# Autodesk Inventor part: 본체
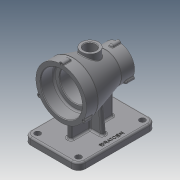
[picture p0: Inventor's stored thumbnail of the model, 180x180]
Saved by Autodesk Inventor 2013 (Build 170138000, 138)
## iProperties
Created: 2020-03
Part Number: 본체
Material: Generic
Document SubType Name: Modeling
Designer: user
Density: 1 g/cm^3
Author: user
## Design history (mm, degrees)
sketch "스케치5"
  geometry: L1 (-50, 44)-(-30, 44); L2 (-30, 44)-(27, 27.5); L3 (27, 27.5)-(50, 27.5); L4 (50, 27.5)-(50, 0); L5 (50, 0)-(-50, 0); L6 (-50, 0)-(-50, 44); 2 further points
  constraints: 12 end point, 3 parallel, 1 coincident, 1 horizontal, 1 midpoint, 1 perpendicular
  dimensions: "d25" = 20 distance of L1.start L1.end; "d27" = 77 distance from line of L2.end L6; "d28" = 100 distance between parallel lines of L4 L6; "d29" = 88 diameter of L1 L5; "d30" = 55 diameter of L3 L5
revolve "회전2" sketch "스케치5" stored, may be unused: angle "d31" = 90 deg
sketch "스케치6"
  geometry: C1 r 44 at (0, 0) reference; C2 r 36 at (0, 0)
  constraints: 1 centre point, 1 coincident
  dimensions: "d32" = 72 diameter of C2
extrude "돌출4" cut sketch "스케치6" distance "d34" = 23; taper "d35" = 0 deg
sketch "스케치7"
  geometry: C1 r 36 at (0, 0) reference; C2 r 26 at (0, 0)
  constraints: 1 centre point, 1 coincident
  dimensions: "d36" = 52 diameter of C2
extrude "돌출5" cut sketch "스케치7" distance "d38" = 47; taper "d39" = 0 deg
sketch "스케치8"
  geometry: C1 r 26 at (0, 0) reference; C2 r 20 at (0, 0)
  constraints: 1 centre point, 1 coincident
  dimensions: "d40" = 40 diameter of C2
extrude "돌출6" cut sketch "스케치8" distance "d42" = 30; taper "d43" = 0 deg
node "작업 평면1"
sketch "스케치9"
  geometry: L1 (-67.5, 47.5)-(67.5, 47.5); L2 (67.5, 47.5)-(67.5, -47.5); L3 (67.5, -47.5)-(-67.5, -47.5); L4 (-67.5, -47.5)-(-67.5, 47.5); L5 (-67.5, 47.5)-(67.5, -47.5); L6 (67.5, 47.5)-(-67.5, -47.5); 1 further point
  constraints: 12 end point, 2 midpoint, 2 parallel, 1 horizontal, 1 perpendicular
  dimensions: "d45" = 135 distance of L2.end L3.end; "d47" = 95 distance of L1.end L2.end
extrude "돌출7" join sketch "스케치9" distance "d48" = 12; taper "d49" = 0 deg
sketch "스케치10"
  geometry: L1 (37, -4)-(-37, -4); L2 (-37, -4)-(-37, 4); L3 (-37, 4)-(37, 4); L4 (37, 4)-(37, -4); L5 (37, -4)-(-37, 4); L6 (-37, -4)-(37, 4); 1 further point
  constraints: 12 end point, 2 midpoint, 2 parallel, 1 horizontal, 1 perpendicular
  dimensions: "d50" = 74 distance of L2.end L3.end; "d52" = 8 distance of L1.end L2.end
extrude "돌출8" join sketch "스케치10" stored distance "d53" = 12; taper "d54" = 0 deg
sketch "스케치11"
  geometry: L1 (-87, 47.5)-(-75, 47.5) reference; L2 (-75, 47.5)-(-75, 4) reference; L3 (-75, 4)-(-35.089, 4) reference; L4 (-35.089, -4)-(-75, -4) reference; L5 (-75, -4)-(-75, -47.5) reference; L6 (-75, -47.5)-(-87, -47.5) reference; L7 (-87, -47.5)-(-87, 47.5) reference; L8 (-28.447, 20.927)-(-75, 25); C1 r 26 at (0, 0) reference; A1 r 35.316 centre (0, 0) between (-35.089, -4) and (-35.089, 4) reference; 1 further point
  constraints: 2 end point, 1 point on circle, 1 point on line
  dimensions: "d56" = 25 vertical distance of point (0, 0) L8.end; "d57" = 95 deg angle of L2 L8
feature "리브1" sketch "스케치11" dims "d58" = 1, "d59" = 8, "d60" = 0, "d61" = 0, "d62" = 1, "d63" = 1
node "작업 평면2"
sketch "스케치12"
  geometry: C1 r 15 at (0, 0); 1 further point
  constraints: 1 centre point, 1 coincident
  dimensions: "d65" = 30 diameter of C1
extrude "돌출9" join sketch "스케치12" stored distance "d67" = 12; taper "d68" = 0 deg
sketch "스케치13"
  geometry: 1 further point
sketch "스케치14"
  geometry: C1 r 15 at (0, 0) reference; C2 r 10 at (0, 0)
  constraints: 1 centre point, 1 coincident
  dimensions: "d69" = 20 diameter of C2
extrude "돌출10" cut sketch "스케치14" distance "d71" = 27.25; taper "d72" = 0 deg
sketch "스케치15"
  geometry: L1 (67.5, 47.5)-(-67.5, 47.5) reference; L2 (-67.5, 47.5)-(-67.5, -47.5) reference; 2 further points
  dimensions: "d73" = 12 distance from line of point (-55.5, 35.5) L1; "d74" = 12 distance from line of point (-55.5, 35.5) L2
hole "구멍1" sketch "스케치15" at (-55.5, 35.5) diameter "d75" = 10; stored, may be unused: countersink angle "d79" = 90 deg, drill point angle "d81" = 118 deg; dims "d76" = 6, "d77" = 4, "d78" = 2, "d80" = 8
fillet "모깎기1" dims "d82" = 12
fillet "모깎기2" dims "d83" = 3
fillet "모깎기3" dims "d84" = 3
fillet "모깎기4" dims "d85" = 3
fillet "모깎기5" dims "d86" = 3
fillet "모깎기6" dims "d87" = 3
sketch "스케치16"
  geometry: C1 r 3.5 at (0, 44); A1 r 44 centre (0, 0) between (0, 44) and (-6.553, -43.509) reference; A2 r 44 centre (0, 0) between (6.553, -43.509) and (-6.553, -43.509) reference; 1 further point
  constraints: 2 point on circle, 1 centre point, 1 coincident
  dimensions: "d88" = 7 diameter of C1
extrude "돌출11" join sketch "스케치16" distance "d90" = 15; taper "d91" = 0 deg
sketch "스케치17"
  geometry: C1 r 20 at (0, 0) reference; C2 r 3.5 at (0, 27.5); 1 further point
  constraints: 2 vertical alignment, 1 centre point, 1 other
  dimensions: "d95" = 7 diameter of C2
extrude "돌출12" join sketch "스케치17" distance "d97" = 15; taper "d98" = 0 deg
sketch "스케치18"
  geometry: A1 r 3.5 centre (38.105, -66) between (36.236, -68.959) and (39.733, -62.902) reference; A2 r 3.5 centre (0, 0) between (3.497, -0.139) and (-3.497, -0.139) reference; A3 r 3.5 centre (-38.105, -66) between (-39.733, -62.902) and (-36.236, -68.959) reference
hole "구멍2" sketch "스케치18" at (0, 0), (38.105, -66), (-38.105, -66) diameter "d102" = 4.134; stored, may be unused: countersink angle "d106" = 90 deg, drill point angle "d108" = 118 deg; dims "d103" = 9, "d104" = 4, "d105" = 2, "d107" = 11
sketch "스케치19"
  geometry: A1 r 3.5 centre (0, 0) between (3.493, -0.223) and (-3.493, -0.223) reference; A2 r 3.5 centre (-23.816, -41.25) between (-25.369, -38.114) and (-21.876, -44.164) reference; A3 r 3.5 centre (23.816, -41.25) between (21.876, -44.164) and (25.369, -38.114) reference
hole "구멍3" sketch "스케치19" at (0, 0), (23.816, -41.25), (-23.816, -41.25) diameter "d109" = 4.134; stored, may be unused: countersink angle "d113" = 90 deg, drill point angle "d115" = 118 deg; dims "d110" = 9, "d111" = 4, "d112" = 2, "d114" = 11
fillet "모깎기7" dims "d116" = 3
fillet "모깎기8" dims "d117" = 1
chamfer "모따기1" distance "d118" = 1; stored, may be unused: second distance "d119" = 2, angle "d120" = 45 deg
fillet "모깎기9" dims "d121" = 1
fillet "모깎기10" dims "d122" = 3
chamfer "모따기2" distance "d123" = 1; stored, may be unused: second distance "d124" = 2, angle "d125" = 45 deg
chamfer "모따기3" distance "d126" = 1; stored, may be unused: second distance "d127" = 2, angle "d128" = 45 deg
node "작업 평면3"
sketch "스케치20"
  geometry: L1 (-55.5, -47.5)-(55.5, -47.5) reference; L2 (67.5, -35.5)-(67.5, 35.5) reference; 2 further points
  constraints: 1 other
  dimensions: "d130" = 10 distance from line of L1 point (0, -37.5); "d131" = 67.5 distance from line of L2 point (0, -37.5)
feature "엠보싱1" sketch "스케치20" dims "d36" = 52, "d132" = 0.5, "d133" = 0
node "솔리드2"
mirror "대칭1"
mirror "대칭2"
mirror "대칭3"
pattern_circular "원형 패턴1" dims angle "d93" = 360 deg
pattern_circular "원형 패턴2" dims angle "d100" = 360 deg
node "절단 모서리 투영1"
other parameters: "d44" = -87, "d64" = 45, "d129" = 18.5
